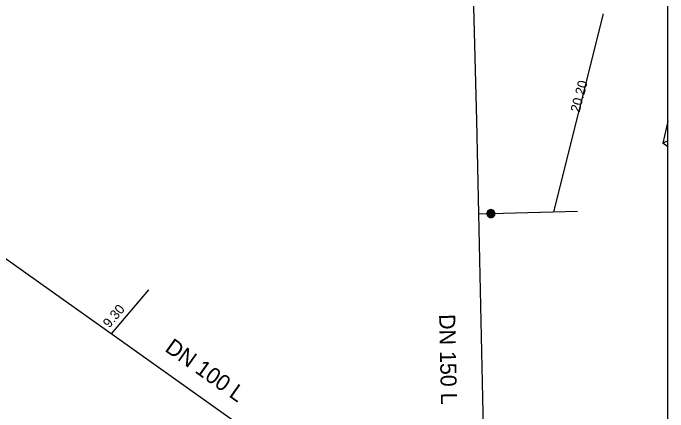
# Model space of a CAD drawing. Extents: x -820257 to -819974, y -1070894 to -1070484.
# Drawn here: x -820057.3 to -819975.6, y -1070844.7 to -1070794.9 of the extents above; entities that cross this region are included whole.
import ezdxf

# ---------------------------------------------------------------- set-up
doc = ezdxf.new("R2010")
doc.units = 0
for name, color, linetype in [('Default', 7, 'Continuous'), ('Oměrka vodovodu', 7, 'Continuous'), ('Oměrka-text', 7, 'Continuous'), ('Přípojka vodovodu', 7, 'Continuous'), ('Přípojkový uzávěr', 7, 'Continuous'), ('Roz-řad', 7, 'Continuous'), ('Roz-řad-popis základní', 7, 'Continuous')]:
    doc.layers.add(name, color=color, linetype=linetype)

msp = doc.modelspace()

# ---------------------------------------------------------------- linework, layer by layer
at = {"layer": 'Default'}
msp.add_line((-819975.603, -1070893.932), (-819975.603, -1070484.403), dxfattribs=at)
at = {"layer": 'Oměrka vodovodu'}
for p, q in [((-819989.814, -1070819.683), (-819983.649, -1070794.964)), ((-819975.603, -1070808.355), (-819976.246, -1070811.111)), ((-819975.603, -1070810.814), (-819976.246, -1070811.111)), ((-819975.603, -1070811.561), (-819976.246, -1070811.111)), ((-820045.019, -1070834.945), (-820040.347, -1070829.452))]:
    msp.add_line(p, q, dxfattribs=at)
at = {"layer": 'Přípojka vodovodu'}
msp.add_lwpolyline([(-819999.183, -1070819.957), (-819997.684, -1070819.913), (-819986.886, -1070819.598)], dxfattribs=at)
at = {"layer": 'Přípojkový uzávěr'}
for points in [[(-819997.699, -1070819.414), (-819997.573, -1070819.41), (-819997.452, -1070819.471), (-819997.33, -1070819.532), (-819997.259, -1070819.65), (-819997.188, -1070819.769), (-819997.184, -1070819.9), (-819997.18, -1070820.029), (-819997.243, -1070820.15), (-819997.305, -1070820.271), (-819997.422, -1070820.34), (-819997.539, -1070820.41), (-819997.67, -1070820.413), (-819997.799, -1070820.417), (-819997.92, -1070820.355), (-819998.041, -1070820.292), (-819998.11, -1070820.175), (-819998.18, -1070820.059), (-819998.184, -1070819.929), (-819998.187, -1070819.798), (-819998.124, -1070819.676), (-819998.06, -1070819.553), (-819997.943, -1070819.485), (-819997.825, -1070819.418), (-819997.699, -1070819.414)], [(-819997.698, -1070819.461), (-819997.812, -1070819.464), (-819997.918, -1070819.526), (-819998.025, -1070819.587), (-819998.083, -1070819.698), (-819998.14, -1070819.809), (-819998.137, -1070819.927), (-819998.133, -1070820.045), (-819998.071, -1070820.151), (-819998.008, -1070820.257), (-819997.898, -1070820.313), (-819997.788, -1070820.37), (-819997.671, -1070820.367), (-819997.553, -1070820.363), (-819997.447, -1070820.3), (-819997.34, -1070820.237), (-819997.284, -1070820.128), (-819997.227, -1070820.019), (-819997.231, -1070819.901), (-819997.234, -1070819.782), (-819997.299, -1070819.675), (-819997.364, -1070819.568), (-819997.473, -1070819.513), (-819997.583, -1070819.457), (-819997.698, -1070819.461)], [(-819997.697, -1070819.495), (-819997.591, -1070819.492), (-819997.489, -1070819.543), (-819997.388, -1070819.594), (-819997.328, -1070819.693), (-819997.268, -1070819.792), (-819997.265, -1070819.902), (-819997.262, -1070820.011), (-819997.314, -1070820.112), (-819997.366, -1070820.213), (-819997.464, -1070820.271), (-819997.563, -1070820.329), (-819997.672, -1070820.332), (-819997.78, -1070820.336), (-819997.882, -1070820.283), (-819997.984, -1070820.231), (-819998.042, -1070820.133), (-819998.099, -1070820.035), (-819998.103, -1070819.926), (-819998.106, -1070819.817), (-819998.053, -1070819.714), (-819997.999, -1070819.612), (-819997.901, -1070819.555), (-819997.802, -1070819.498), (-819997.697, -1070819.495)], [(-819997.696, -1070819.539), (-819997.852, -1070819.543), (-819997.958, -1070819.656), (-819998.063, -1070819.769), (-819998.059, -1070819.925), (-819998.054, -1070820.08), (-819997.941, -1070820.187), (-819997.828, -1070820.293), (-819997.674, -1070820.288), (-819997.518, -1070820.284), (-819997.411, -1070820.171), (-819997.304, -1070820.058), (-819997.309, -1070819.903), (-819997.313, -1070819.747), (-819997.426, -1070819.641), (-819997.538, -1070819.534), (-819997.696, -1070819.539)], [(-819997.694, -1070819.585), (-819997.557, -1070819.581), (-819997.459, -1070819.674), (-819997.361, -1070819.767), (-819997.357, -1070819.903), (-819997.353, -1070820.039), (-819997.446, -1070820.138), (-819997.539, -1070820.237), (-819997.675, -1070820.241), (-819997.812, -1070820.245), (-819997.91, -1070820.152), (-819998.009, -1070820.058), (-819998.013, -1070819.922), (-819998.017, -1070819.786), (-819997.924, -1070819.687), (-819997.831, -1070819.589), (-819997.694, -1070819.585)], [(-819997.693, -1070819.624), (-819997.813, -1070819.628), (-819997.895, -1070819.715), (-819997.977, -1070819.802), (-819997.973, -1070819.921), (-819997.97, -1070820.041), (-819997.883, -1070820.123), (-819997.796, -1070820.205), (-819997.676, -1070820.201), (-819997.557, -1070820.198), (-819997.475, -1070820.111), (-819997.393, -1070820.024), (-819997.396, -1070819.904), (-819997.4, -1070819.785), (-819997.486, -1070819.703), (-819997.573, -1070819.621), (-819997.693, -1070819.624)], [(-819997.692, -1070819.664), (-819997.587, -1070819.661), (-819997.512, -1070819.732), (-819997.437, -1070819.803), (-819997.434, -1070819.907), (-819997.431, -1070820.01), (-819997.502, -1070820.085), (-819997.573, -1070820.16), (-819997.677, -1070820.164), (-819997.78, -1070820.167), (-819997.855, -1070820.096), (-819997.931, -1070820.025), (-819997.934, -1070819.921), (-819997.937, -1070819.817), (-819997.866, -1070819.742), (-819997.796, -1070819.667), (-819997.692, -1070819.664)], [(-819997.69, -1070819.71), (-819997.775, -1070819.713), (-819997.832, -1070819.774), (-819997.89, -1070819.835), (-819997.887, -1070819.919), (-819997.885, -1070820.004), (-819997.824, -1070820.061), (-819997.763, -1070820.119), (-819997.678, -1070820.116), (-819997.594, -1070820.114), (-819997.537, -1070820.053), (-819997.479, -1070819.992), (-819997.481, -1070819.907), (-819997.484, -1070819.823), (-819997.545, -1070819.765), (-819997.606, -1070819.708), (-819997.69, -1070819.71)], [(-819997.689, -1070819.745), (-819997.619, -1070819.743), (-819997.568, -1070819.79), (-819997.518, -1070819.838), (-819997.516, -1070819.908), (-819997.514, -1070819.979), (-819997.562, -1070820.029), (-819997.61, -1070820.079), (-819997.679, -1070820.082), (-819997.75, -1070820.084), (-819997.8, -1070820.036), (-819997.851, -1070819.988), (-819997.853, -1070819.918), (-819997.855, -1070819.848), (-819997.807, -1070819.797), (-819997.76, -1070819.747), (-819997.689, -1070819.745)], [(-819997.688, -1070819.789), (-819997.74, -1070819.79), (-819997.775, -1070819.828), (-819997.81, -1070819.866), (-819997.809, -1070819.917), (-819997.807, -1070819.969), (-819997.77, -1070820.005), (-819997.732, -1070820.04), (-819997.681, -1070820.039), (-819997.628, -1070820.037), (-819997.593, -1070819.999), (-819997.557, -1070819.962), (-819997.559, -1070819.91), (-819997.56, -1070819.858), (-819997.598, -1070819.823), (-819997.635, -1070819.787), (-819997.688, -1070819.789)], [(-819997.687, -1070819.836), (-819997.653, -1070819.835), (-819997.63, -1070819.856), (-819997.607, -1070819.878), (-819997.606, -1070819.911), (-819997.605, -1070819.944), (-819997.627, -1070819.967), (-819997.649, -1070819.991), (-819997.682, -1070819.992), (-819997.714, -1070819.993), (-819997.738, -1070819.97), (-819997.761, -1070819.948), (-819997.762, -1070819.916), (-819997.763, -1070819.883), (-819997.741, -1070819.86), (-819997.719, -1070819.836), (-819997.687, -1070819.836)], [(-819997.686, -1070819.867), (-819997.705, -1070819.867), (-819997.718, -1070819.881), (-819997.732, -1070819.895), (-819997.731, -1070819.915), (-819997.731, -1070819.935), (-819997.717, -1070819.948), (-819997.702, -1070819.961), (-819997.683, -1070819.96), (-819997.663, -1070819.96), (-819997.65, -1070819.946), (-819997.637, -1070819.932), (-819997.637, -1070819.912), (-819997.638, -1070819.892), (-819997.652, -1070819.879), (-819997.666, -1070819.866), (-819997.686, -1070819.867)]]:
    msp.add_open_spline(points, degree=3, dxfattribs=at)
at = {"layer": 'Roz-řad'}
for points in [[(-819998.171, -1070870.117), (-819998.405, -1070853.152), (-819998.628, -1070844.86), (-819999.183, -1070819.957), (-819999.443, -1070808.28), (-820000.085, -1070782.958), (-820000.381, -1070772.161), (-820000.485, -1070768.618)], [(-820009.275, -1070860.089), (-820009.863, -1070859.992), (-820044.329, -1070835.435), (-820068.948, -1070817.938), (-820083.25, -1070815.478)]]:
    msp.add_lwpolyline(points, dxfattribs=at)

# ---------------------------------------------------------------- texts
at = {"layer": 'Oměrka-text'}
for s, rotation, p in [('20.20', 74.99594, (-819986.634, -1070807.349)), (' 9.30', 49.61763, (-820045.58, -1070834.615))]:
    msp.add_text(s, height=1.2, rotation=rotation, dxfattribs=at).set_placement(p)
at = {"layer": 'Roz-řad-popis základní'}
for s, rotation, p in [('DN 150 L', 271.27672, (-820004.147, -1070832.489)), ('DN 100 L', 324.53017, (-820038.47, -1070837.005))]:
    msp.add_text(s, height=2, rotation=rotation, dxfattribs=at).set_placement(p)

doc.saveas('drawing.dxf')
